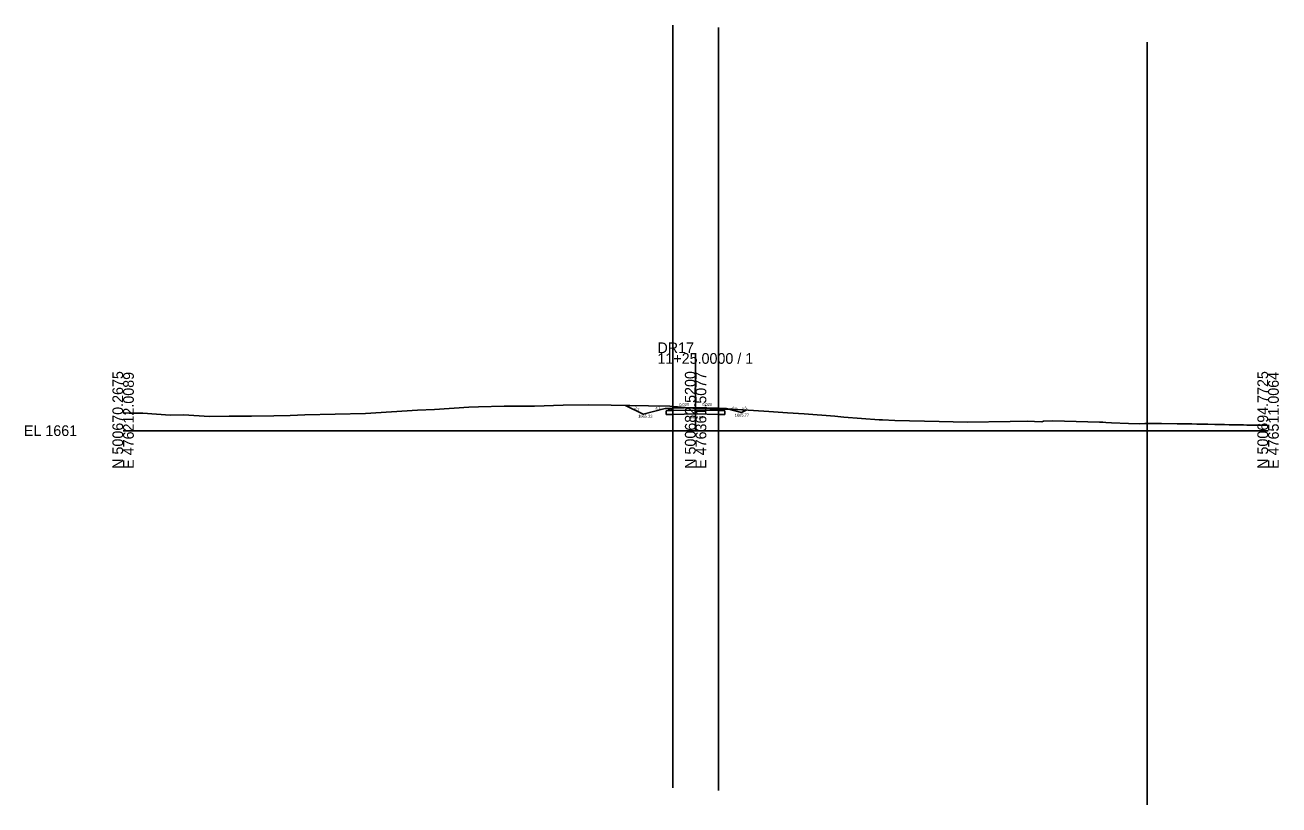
# Model space of a CAD drawing. Extents: x -26 to 303, y -96 to 3030.
# Drawn here: x -25.7 to 302.8, y 2401.9 to 2606.3 of the extents above; entities that cross this region are included whole.
import ezdxf

# ---------------------------------------------------------------- set-up
doc = ezdxf.new("R2010")
doc.units = 0
for name, color, linetype in [('Exist Cross Section Cell', 7, 'Continuous'), ('Exist XS Center Line Elevation Label', 7, 'Continuous'), ('Exist XS Ground Line', 7, 'Continuous'), ('Prop CMT Shallow Undercut Boundary', 7, 'Continuous'), ('Prop XS Ditch Slope Text', 7, 'Continuous'), ('Prop XS Ditch Standard Text', 7, 'Continuous'), ('Prop XS Earthwork Shape', 7, 'Continuous'), ('Prop XS EOT Tick Mark', 7, 'Continuous'), ('Prop XS Finish Grade', 7, 'Continuous'), ('Prop XS Finish Grade Earthwork', 7, 'Continuous'), ('Prop XS Finish Grade Pavement', 7, 'Continuous'), ('Prop XS Pvmt Edge Slope', 7, 'Continuous'), ('Prop XS SE Text', 7, 'Continuous'), ('Prop XS Shoulder Borrow Shape', 7, 'Continuous'), ('Prop XS Side Slope Text', 7, 'Continuous'), ('Prop XS Subgrade Earthwork', 7, 'Continuous'), ('Scratch_Level_2', 7, 'Continuous')]:
    doc.layers.add(name, color=color, linetype=linetype)

msp = doc.modelspace()

# ---------------------------------------------------------------- linework, layer by layer
at = {"layer": 'Exist Cross Section Cell'}
for p, q in [((150, 2500), (150, 2520.33)), ((0, 2500), (150, 2500)), ((150, 2500), (300, 2500))]:
    msp.add_line(p, q, dxfattribs=at)
at = {"layer": 'Exist XS Ground Line'}
msp.add_lwpolyline([(0, 2504.71), (1.54, 2504.62), (5.2, 2504.6), (12.28, 2504.09), (15.89, 2504.11), (22.52, 2503.75), (27.82, 2503.82), (33.65, 2503.77), (39.45, 2503.88), (43.76, 2503.98), (47.61, 2504.11), (63.52, 2504.54), (77.12, 2505.41), (81.59, 2505.56), (90.54, 2506.2), (93.11, 2506.23), (99.82, 2506.4), (107.78, 2506.41), (115.28, 2506.7), (121.94, 2506.78), (127.87, 2506.66), (137.63, 2506.54), (143.22, 2506.39), (150.2, 2505.84), (159.76, 2505.6), (169.21, 2505.02), (174.06, 2504.66), (178.47, 2504.43), (186.48, 2503.78), (188.82, 2503.53), (198.13, 2502.87), (199.01, 2502.81), (202.21, 2502.66), (213.81, 2502.38), (221.14, 2502.24), (232.41, 2502.38), (236.91, 2502.46), (240.7, 2502.33), (241.13, 2502.47), (243.57, 2502.58), (255.83, 2502.24), (256.24, 2502.24), (256.71, 2502.2), (257.53, 2502.13), (258.93, 2502.04), (263.41, 2501.86), (266.35, 2501.75), (267.74, 2501.89), (269.46, 2501.88), (272.07, 2501.85), (276.15, 2501.81), (278.41, 2501.79), (279.39, 2501.78), (279.99, 2501.77), (281.3, 2501.74), (283.56, 2501.68), (284.25, 2501.67), (286.05, 2501.64), (287.09, 2501.62), (288.56, 2501.59), (289.83, 2501.56), (291.06, 2501.53), (292.11, 2501.52), (293.57, 2501.49), (294.43, 2501.48), (296.08, 2501.46), (296.76, 2501.44), (298.59, 2501.4), (300, 2501.37)], dxfattribs=at)
at = {"layer": 'Prop CMT Shallow Undercut Boundary'}
for p, q in [((142.32, 2505.23), (144, 2505.27)), ((142.32, 2504.23), (142.32, 2505.23)), ((142.32, 2505.23), (142.32, 2504.23)), ((144, 2504.27), (142.32, 2504.23)), ((142.32, 2504.23), (144, 2504.27)), ((144, 2505.27), (150, 2505.39)), ((150, 2505.39), (144, 2505.27)), ((150, 2504.39), (144, 2504.27)), ((144, 2504.27), (150, 2504.39)), ((150, 2505.39), (156, 2505.27)), ((156, 2505.27), (150, 2505.39)), ((156, 2504.27), (150, 2504.39)), ((150, 2504.39), (156, 2504.27)), ((156, 2505.27), (157.68, 2505.23)), ((156.68, 2505.25), (156, 2505.27)), ((157.68, 2504.23), (156, 2504.27)), ((156, 2504.27), (157.68, 2504.23)), ((157.68, 2505.23), (156.68, 2505.25)), ((157.68, 2505.23), (157.68, 2504.23)), ((157.68, 2504.23), (157.68, 2505.23))]:
    msp.add_line(p, q, dxfattribs=at)
msp.add_lwpolyline([(144, 2505.27), (143.32, 2505.25), (142.32, 2505.23)], dxfattribs=at)
at = {"layer": 'Prop XS Earthwork Shape'}
for points in [[(156, 2505.27), (156.68, 2505.25), (157.09, 2505.66), (150.2, 2505.84), (143.22, 2506.39), (137.63, 2506.54), (131.67, 2506.61), (136.23, 2504.33), (142, 2505.77), (142.74, 2505.83), (143.32, 2505.25), (144, 2505.27), (150, 2505.39)], [(158, 2505.77), (158.58, 2505.63), (157.09, 2505.66), (157.26, 2505.83)], [(158.58, 2505.63), (159.76, 2505.6), (163.23, 2505.39), (162, 2504.77)]]:
    msp.add_lwpolyline(points, close=True, dxfattribs=at)
at = {"layer": 'Prop XS EOT Tick Mark'}
for p, q in [((144, 2505.93), (144, 2506.93)), ((156, 2505.93), (156, 2506.93))]:
    msp.add_line(p, q, dxfattribs=at)
at = {"layer": 'Prop XS Finish Grade'}
for p, q in [((144, 2505.93), (142.74, 2505.83)), ((156, 2505.93), (157.26, 2505.83))]:
    msp.add_line(p, q, dxfattribs=at)
at = {"layer": 'Prop XS Finish Grade Earthwork'}
for p, q in [((136.23, 2504.33), (131.67, 2506.61)), ((142, 2505.77), (136.23, 2504.33)), ((142.74, 2505.83), (142, 2505.77)), ((157.26, 2505.83), (158, 2505.77)), ((158, 2505.77), (162, 2504.77)), ((162, 2504.77), (163.23, 2505.39))]:
    msp.add_line(p, q, dxfattribs=at)
at = {"layer": 'Prop XS Finish Grade Pavement'}
for p, q in [((144, 2505.93), (150, 2506.05)), ((150, 2506.05), (156, 2505.93))]:
    msp.add_line(p, q, dxfattribs=at)
at = {"layer": 'Prop XS Pvmt Edge Slope'}
for p, q in [((144, 2505.93), (143.32, 2505.25)), ((156, 2505.93), (156.68, 2505.25))]:
    msp.add_line(p, q, dxfattribs=at)
at = {"layer": 'Prop XS Shoulder Borrow Shape'}
for points in [[(144, 2505.93), (142.74, 2505.83), (143.32, 2505.25)], [(156, 2505.93), (157.26, 2505.83), (156.68, 2505.25)]]:
    msp.add_lwpolyline(points, close=True, dxfattribs=at)
at = {"layer": 'Prop XS Subgrade Earthwork'}
for p, q in [((143.32, 2505.25), (142.74, 2505.83)), ((144, 2505.27), (143.32, 2505.25)), ((150, 2505.39), (144, 2505.27)), ((156, 2505.27), (150, 2505.39)), ((156, 2505.27), (156.68, 2505.25)), ((156.68, 2505.25), (157.26, 2505.83))]:
    msp.add_line(p, q, dxfattribs=at)
at = {"layer": 'Scratch_Level_2'}
for p, q in [((144, 2606.33), (144, 2406.33)), ((156, 2605.69), (156, 2405.69)), ((268.28, 2601.89), (268.28, 2401.89))]:
    msp.add_line(p, q, dxfattribs=at)

# ---------------------------------------------------------------- texts
at = {"layer": 'Exist Cross Section Cell'}
for s, p in [('11+25.0000 / 1', (140, 2517.53)), ('DR17', (140, 2520.33)), ('EL 1661', (-26, 2498.6))]:
    msp.add_text(s, height=2.8, dxfattribs=at).set_placement(p)
for s, p in [('N 500670.2675', (0, 2490)), ('E 476212.0089', (2.8, 2490)), ('N 500682.5200', (150, 2490)), ('E 476361.5077', (152.8, 2490)), ('N 500694.7725', (300, 2490)), ('E 476511.0064', (302.8, 2490))]:
    msp.add_text(s, height=2.8, rotation=90, dxfattribs=at).set_placement(p)
at = {"layer": 'Exist XS Center Line Elevation Label'}
msp.add_text('1666.86', height=0.75, dxfattribs=at).set_placement((148.28, 2503.11))
at = {"layer": 'Prop XS Ditch Slope Text'}
for rotation, p in [(14.0362, (139.53, 2505.4)), (345.9638, (159.33, 2505.66))]:
    msp.add_text('4:1', height=0.75, rotation=rotation, dxfattribs=at).set_placement(p)
at = {"layer": 'Prop XS Ditch Standard Text'}
for s, p in [('1665.33', (134.95, 2503.41)), ('1665.77', (160.25, 2503.69))]:
    msp.add_text(s, height=0.75, dxfattribs=at).set_placement(p)
at = {"layer": 'Prop XS SE Text'}
for rotation, p in [(1.1458, (145.71, 2506.47)), (358.8542, (151.71, 2506.52))]:
    msp.add_text('0.020', height=0.75, rotation=rotation, dxfattribs=at).set_placement(p)
at = {"layer": 'Prop XS Side Slope Text'}
for rotation, p in [(333.4349, (133.83, 2505.73)), (26.5651, (162.33, 2505.18))]:
    msp.add_text('2:1', height=0.75, rotation=rotation, dxfattribs=at).set_placement(p)

doc.saveas('drawing.dxf')
